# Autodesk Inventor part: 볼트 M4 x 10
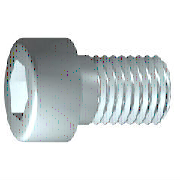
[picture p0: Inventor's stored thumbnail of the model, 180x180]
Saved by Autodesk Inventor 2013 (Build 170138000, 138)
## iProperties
IsCustomPart: 0
Created: 2016-04
Part Number: 볼트 M4 x 10
Material: 강철, 연강
Description: 6각머리 태핑 나사
Document SubType Name: Modeling
Standard: KS B 1003
Designer: mdu
Standards Organization: KS
Language: ko-KR
Size Designation: M 4 x 10
Categories: <MemberInstance><Categories><Category DisplayName="조임쇠" InternalName="e4da775c-781d-43d5-af7c-5136215cf5a6" Mnemonic="FSTN"><Category DisplayName="볼트" InternalN
Density: 7.86 g/cm^3
Mass: 2.0371 g
Surface Area: 3.0572 cm^2
Volume: 0.259174 cm^3
Author: mdu
Revision Number: 1
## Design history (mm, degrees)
sketch "스케치1"
  geometry: L1 (-1, 0)-(10, 0); L2 (10, 0)-(10, 2); L3 (10, 2)-(1.75, 2); L4 (1.75, 2)-(1.32, 2); L5 (1.32, 2)-(0, 2); L6 (0, 2)-(0, 3.5); L7 (0, 3.5)-(-4, 3.5); L8 (-4, 3.5)-(-4, 1.732); L9 (-4, 1.732)-(-2, 1.732); L10 (-2, 1.732)-(-1, 0); L11 (-6.8, 0)-(12.8, 0) reference; L12 (0, -0.7)-(0, 4.2) reference; L13 (1.75, 2)-(0, 2)
  constraints: 22 end point, 6 parallel, 2 collinear, 2 perpendicular, 1 horizontal, 1 point on line
  dimensions: "d1" = 8.25 distance from line of L3.end L2 (= GEL); "d2" = 0.42952 distance of L4.end L3.end (computed from GAL); "d3" = 4 distance between parallel lines of L8 L6 (= KOH); "d4" = 2 distance of L8.end L9.end (= INTI); "d5" = 60 deg angle of L10 L1; "d6" = 4 diameter of L3 L1 (= GD); "d7" = 4 diameter of L5 L1 (= BDM); "d8" = 3.4641 diameter of L9 L1 (= 1.1547 x SW); "d9" = 7 diameter of L7 L1 (= KOD); "d26" = 10 distance between parallel lines of L12 L2 (= NLG)
revolve "본체" sketch "스케치1" stored, may be unused: angle "d10" = 90 deg
sketch "스케치2"
  geometry: L1 (0, -4.9)-(0, 4.9) reference; L2 (-4.9, 0)-(4.9, 0) reference; L3 (1.732, 0)-(0.866, -1.5); L4 (0.866, -1.5)-(-0.866, -1.5); L5 (-0.866, -1.5)-(-1.732, 0); L6 (-1.732, 0)-(-0.866, 1.5); L7 (-0.866, 1.5)-(0.866, 1.5); L8 (0.866, 1.5)-(1.732, 0); 2 further points
  constraints: 12 end point, 1 coincident, 1 horizontal alignment, 1 point on line, 12 other
extrude "슬롯" join sketch "스케치2" stored distance "d11" = 10; taper "d12" = 0 deg
workplane "Work Plane1"
fillet "Fillet2" dims "d30" = 0.1 (= R)
body "Solid1"
fillet "모깎기1" dims "d17" = 0.4 (= RR)
feature "스레드" dims "d13" = 8.25 (= GEL), "d14" = 0
chamfer "모따기1" distance "d15" = 0.42941 (= -0.5 x SPD + 0.5 x GD); stored, may be unused: second distance "d16" = 0.42941 (= GUL), angle "d27" = 45 deg
other parameters: "GD" = 4 (= NND) [user parameter; used in 2 equation terms], "NLG" = 10 [user parameter; used in 1 equation term], "GEL" = 8.25 [user parameter; used in 2 equation terms], "KOD" = 7 [user parameter; used in 1 equation term], "KOH" = 4 [user parameter; used in 1 equation term], "INTI" = 2 [user parameter; used in 1 equation term], "GAL" = 0.42941 (= 0.61345 x PTC) [user parameter; used in 1 equation term], "GUL" = 0.42941 (= 0.61345 x PTC) [user parameter; used in 1 equation term], "BDM" = 4 (= NND) [user parameter; used in 1 equation term], "SW" = 3 [user parameter; used in 2 equation terms], "RR" = 0.4 [user parameter; used in 1 equation term], "SPD" = 3.14117 (= NND - 1.2269 x PTC) [user parameter; used in 1 equation term], "d19" = 0, "d28" = 0, "d29" = 0, "R" = 0.1 [user parameter; used in 1 equation term], "PHH" = 0.2 [user parameter], "GD1" = 3.14117 (= THREADDIA - 1.2269 x PTC) [user parameter], "THREADDIA" = 4 [user parameter; used in 1 equation term], "FAWI" = 45 deg [user parameter], "TPU" = 14.28571 (computed from PTC) [user parameter], "PTC" = 0.7 [user parameter; used in 5 equation terms], "NND" = 4 [user parameter; used in 3 equation terms], "TOA" = 30 deg [user parameter], "E0" = 3.465 (= 1.155 x SW) [user parameter]
